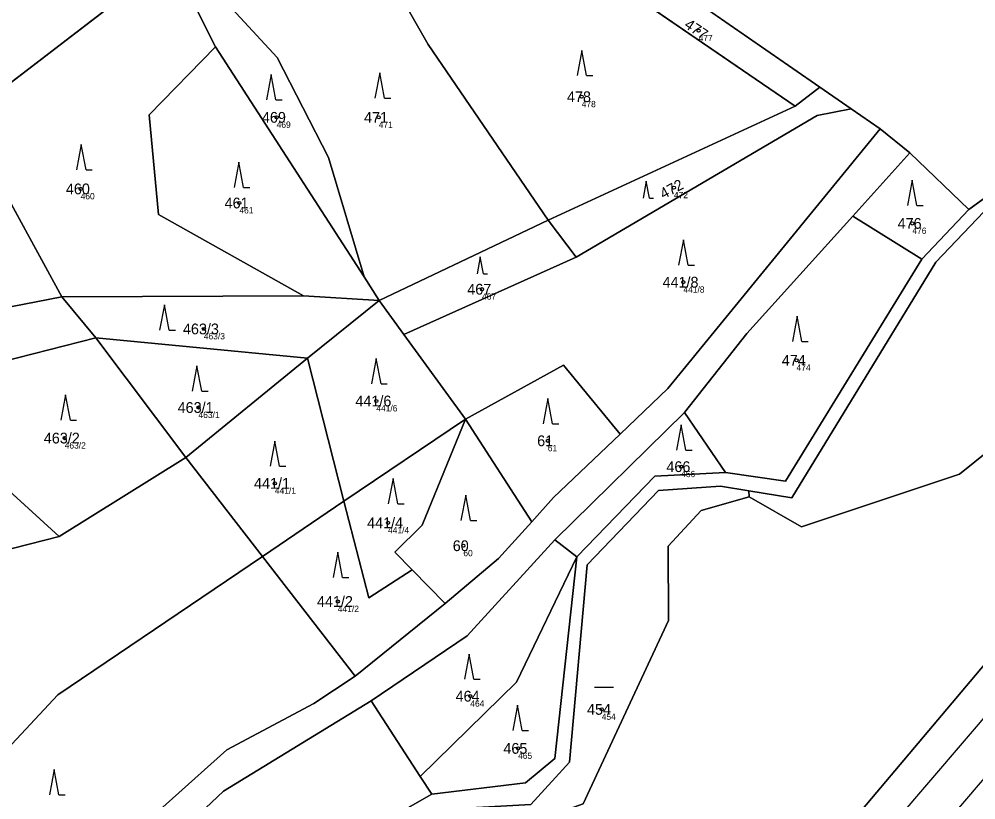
# Model space of a CAD drawing. Extents: x -554500 to -548272, y -1079733 to -1073730.
# Drawn here: x -551641.1 to -551489.7, y -1075645.3 to -1075521.8 of the extents above; entities that cross this region are included whole.
import ezdxf

# ---------------------------------------------------------------- set-up
doc = ezdxf.new("R2010")
doc.units = 0
for name, color, linetype in [('Definiční body', 7, 'Continuous'), ('Hranice parcel', 7, 'Continuous'), ('Parcelní čísla', 7, 'Continuous'), ('Polygon ku', 7, 'Continuous'), ('Polygon parcely', 7, 'Continuous'), ('Vnitřní kresba', 7, 'Continuous'), ('Značky kultur', 7, 'Continuous')]:
    doc.layers.add(name, color=color, linetype=linetype)

msp = doc.modelspace()

# ---------------------------------------------------------------- linework, layer by layer
at = {"layer": 'Definiční body'}
for centre in [(-551533.57, -1075523.64994), (-551552.07, -1075534.09994), (-551600.33, -1075537.35994), (-551584.18, -1075537.36994), (-551631.34, -1075548.67994), (-551537.48, -1075548.48994), (-551606.23, -1075550.90994), (-551499.76, -1075554.13994), (-551535.98, -1075563.43994), (-551567.84, -1075564.54994), (-551611.85, -1075570.82994), (-551518.08, -1075575.78994), (-551612.69, -1075583.25994), (-551584.56, -1075582.22994), (-551633.86, -1075588.09994), (-551557.43, -1075588.52994), (-551536.34, -1075592.61994), (-551600.61, -1075595.25994), (-551582.71, -1075601.49994), (-551570.79, -1075605.12994), (-551590.65, -1075613.94994), (-551569.69, -1075628.92994), (-551548.9, -1075631.01994), (-551562.13, -1075637.18994)]:
    msp.add_circle(centre, 0.25, dxfattribs=at)
at = {"layer": 'Hranice parcel'}
for p, q in [((-551549.56, -1075508.24), (-551514.4, -1075532.57)), ((-551554, -1075511.14), (-551518.28, -1075535.59)), ((-551616.94, -1075512.32), (-551649.75, -1075537.47)), ((-551609.99, -1075526.19), (-551616.94, -1075512.32)), ((-551586.49, -1075562.61), (-551609.99, -1075526.19)), ((-551514.4, -1075532.57), (-551518.28, -1075535.59)), ((-551514.4, -1075532.57), (-551509.43, -1075536.01)), ((-551490.82, -1075551.95), (-551465.77, -1075533.69)), ((-551518.28, -1075535.59), (-551557.39, -1075553.61)), ((-551509.43, -1075536.01), (-551504.87, -1075539.17)), ((-551634.33, -1075565.77), (-551649.75, -1075537.47)), ((-551504.87, -1075539.17), (-551500.16, -1075542.97)), ((-551500.16, -1075542.97), (-551509.17, -1075552.97)), ((-551500.16, -1075542.97), (-551490.82, -1075551.95)), ((-551498.28, -1075559.77), (-551490.82, -1075551.95)), ((-551557.39, -1075553.61), (-551584.08, -1075566.35)), ((-551552.96, -1075559.5), (-551557.39, -1075553.61)), ((-551498.28, -1075559.77), (-551509.17, -1075552.97)), ((-551580.19, -1075571.7), (-551552.96, -1075559.5)), ((-551584.08, -1075566.35), (-551586.49, -1075562.61)), ((-551634.33, -1075565.77), (-551596.07, -1075565.58)), ((-551628.95, -1075572.25), (-551634.33, -1075565.77)), ((-551596.07, -1075565.58), (-551584.08, -1075566.35)), ((-551584.08, -1075566.35), (-551595.46, -1075575.44)), ((-551584.08, -1075566.35), (-551580.19, -1075571.7)), ((-551595.46, -1075575.44), (-551628.95, -1075572.25)), ((-551628.95, -1075572.25), (-551614.69, -1075591.16)), ((-551570.46, -1075585.08), (-551580.19, -1075571.7)), ((-551595.46, -1075575.44), (-551614.69, -1075591.16)), ((-551589.67, -1075598.07), (-551595.46, -1075575.44)), ((-551535.81, -1075584.07), (-551556.33, -1075604.19)), ((-551529.31, -1075593.53), (-551535.81, -1075584.07)), ((-551570.46, -1075585.08), (-551589.67, -1075598.07)), ((-551559.98, -1075601.33), (-551570.46, -1075585.08)), ((-551634.75, -1075603.68), (-551650.56, -1075589.25)), ((-551614.69, -1075591.16), (-551634.75, -1075603.68)), ((-551614.69, -1075591.16), (-551602.58, -1075606.81)), ((-551525.61, -1075596.45), (-551525.59, -1075597.39)), ((-551602.58, -1075606.81), (-551589.67, -1075598.07)), ((-551644.48, -1075606.14), (-551634.75, -1075603.68)), ((-551552.81, -1075606.86), (-551556.33, -1075604.19)), ((-551602.58, -1075606.81), (-551587.91, -1075625.77)), ((-551573.69, -1075614.27), (-551578.9, -1075608.93)), ((-551587.91, -1075625.77), (-551573.69, -1075614.27)), ((-551577.6, -1075641.64), (-551585.38, -1075629.65)), ((-551575.78, -1075644.44), (-551577.6, -1075641.64))]:
    msp.add_line(p, q, dxfattribs=at)
for points in [[(-551557.39, -1075553.61), (-551576.36, -1075525.85), (-551588.07, -1075505.25)], [(-551586.49, -1075562.61), (-551592.14, -1075543.72), (-551600.22, -1075527.89), (-551609.92, -1075517.35)], [(-551596.07, -1075565.58), (-551619.02, -1075552.73), (-551620.47, -1075536.97), (-551609.99, -1075526.19)], [(-551465.28, -1075534.16), (-551488.46, -1075552.33), (-551496.05, -1075560.25), (-551518.81, -1075597.54), (-551525.61, -1075596.45)], [(-551552.96, -1075559.5), (-551514.83, -1075537.09), (-551509.43, -1075536.01)], [(-551504.87, -1075539.17), (-551538.42, -1075580.28), (-551545.97, -1075587.48)], [(-551509.17, -1075552.97), (-551525.92, -1075571.57), (-551535.81, -1075584.07)], [(-551529.31, -1075593.53), (-551519.81, -1075594.93), (-551498.28, -1075559.77)], [(-551634.33, -1075565.77), (-551650.34, -1075568.84), (-551660.13, -1075577.33)], [(-551650.56, -1075589.25), (-551643.78, -1075576.01), (-551628.95, -1075572.25)], [(-551545.97, -1075587.48), (-551554.92, -1075576.55), (-551570.46, -1075585.08)], [(-551459.35, -1075584.9), (-551470.49, -1075576.27), (-551492.3, -1075593.8), (-551517.28, -1075602.15), (-551525.59, -1075597.39)], [(-551570.46, -1075585.08), (-551577.29, -1075601.89), (-551581.63, -1075606.13), (-551578.9, -1075608.93)], [(-551560.75, -1075872.41), (-551564.05, -1075824.19), (-551568.79, -1075795.75), (-551568.78, -1075755.17), (-551558.84, -1075728.67), (-551539.1, -1075684.12), (-551467.34, -1075599.01), (-551459.35, -1075584.9)], [(-551545.97, -1075587.48), (-551556.55, -1075597.52), (-551559.98, -1075601.33)], [(-551552.81, -1075606.86), (-551540.49, -1075594.12), (-551529.31, -1075593.53)], [(-551525.61, -1075596.45), (-551530.1, -1075595.73), (-551539.9, -1075596.37), (-551551.19, -1075608.13), (-551553.99, -1075639.39), (-551560.09, -1075646.07), (-551576.31, -1075646.95), (-551596.7, -1075664.95)], [(-551525.59, -1075597.39), (-551533.17, -1075599.56), (-551538.37, -1075605.21), (-551538.32, -1075616.93), (-551551.82, -1075645.98), (-551566.19, -1075651.07), (-551581.91, -1075665.22), (-551587.04, -1075663.89), (-551594.66, -1075668.19)], [(-551578.9, -1075608.93), (-551585.75, -1075613.38), (-551589.67, -1075598.07)], [(-551559.98, -1075601.33), (-551565.23, -1075607.16), (-551573.69, -1075614.27)], [(-551556.33, -1075604.19), (-551570.2, -1075619.38), (-551585.38, -1075629.65)], [(-551602.58, -1075606.81), (-551634.94, -1075628.7), (-551671.23, -1075667.6), (-551664.02, -1075672.26), (-551677.4, -1075709.23)], [(-551577.6, -1075641.64), (-551562.37, -1075626.71), (-551552.81, -1075606.86)], [(-551575.78, -1075644.44), (-551560.93, -1075642.63), (-551556.33, -1075638.76), (-551552.81, -1075606.86)], [(-551587.91, -1075625.77), (-551594.43, -1075630.08), (-551608.2, -1075637.39), (-551625.4, -1075652.79), (-551648.43, -1075682.33), (-551654.36, -1075696.39), (-551656.22, -1075714.82), (-551656.78, -1075734.63), (-551655.54, -1075755.99)], [(-551585.38, -1075629.65), (-551608.75, -1075643.98), (-551622.11, -1075656.61), (-551628.14, -1075663.2), (-551643.57, -1075684.48), (-551647.9, -1075692.99), (-551651.95, -1075709.72), (-551652.68, -1075745.12)], [(-551643.77, -1075728.23), (-551642.39, -1075720.35), (-551630.63, -1075693.57), (-551623.73, -1075689.94), (-551613.7, -1075675.62), (-551597.79, -1075662.9), (-551583.64, -1075648.93), (-551575.78, -1075644.44)]]:
    msp.add_lwpolyline(points, dxfattribs=at)
at = {"layer": 'Polygon ku'}
msp.add_lwpolyline([(-551372.54, -1075528.44), (-551376.14, -1075528.04), (-551396.16, -1075525.8), (-551404.54, -1075528.55), (-551406.9, -1075529.33), (-551413.37, -1075528.01), (-551428.8, -1075524.85), (-551451.89, -1075526.88), (-551457.05, -1075527.33), (-551458.03, -1075528.04), (-551465.77, -1075533.69), (-551490.82, -1075551.95), (-551500.16, -1075542.97), (-551504.87, -1075539.17), (-551509.43, -1075536.01), (-551514.4, -1075532.57), (-551549.56, -1075508.24)], dxfattribs=at)
at = {"layer": 'Polygon parcely'}
for points in [[(-551908.78, -1075679.57), (-551762.84, -1075664.65), (-551729.75, -1075668.79), (-551720.31, -1075645.47), (-551712.09, -1075636.75), (-551699.35, -1075596.46), (-551669.74, -1075565.36), (-551659.13, -1075548.13), (-551649.75, -1075537.47), (-551616.94, -1075512.32), (-551603.86, -1075489.16), (-551600.43, -1075483.34), (-551622.04, -1075477.44), (-551671.35, -1075475.23), (-551688.86, -1075545.18), (-551707.78, -1075585.61), (-551761.67, -1075597.82), (-551774, -1075594.76), (-551845.13, -1075640.16)], [(-551557.39, -1075553.61), (-551576.36, -1075525.85), (-551588.07, -1075505.25), (-551593.22, -1075498.92), (-551609.92, -1075517.35), (-551600.22, -1075527.89), (-551592.14, -1075543.72), (-551586.49, -1075562.61), (-551584.08, -1075566.35)], [(-551577.03, -1075499.37), (-551588.07, -1075505.25), (-551576.36, -1075525.85), (-551557.39, -1075553.61), (-551518.28, -1075535.59), (-551554, -1075511.14), (-551565.72, -1075518.65), (-551572.3, -1075503.16)], [(-551549.56, -1075508.24), (-551554, -1075511.14), (-551518.28, -1075535.59), (-551514.4, -1075532.57)], [(-551619.02, -1075552.73), (-551620.47, -1075536.97), (-551609.99, -1075526.19), (-551616.94, -1075512.32), (-551649.75, -1075537.47), (-551634.33, -1075565.77), (-551596.07, -1075565.58)], [(-551586.49, -1075562.61), (-551592.14, -1075543.72), (-551600.22, -1075527.89), (-551609.92, -1075517.35), (-551616.94, -1075512.32), (-551609.99, -1075526.19)], [(-551609.99, -1075526.19), (-551620.47, -1075536.97), (-551619.02, -1075552.73), (-551596.07, -1075565.58), (-551584.08, -1075566.35), (-551586.49, -1075562.61)], [(-551514.4, -1075532.57), (-551518.28, -1075535.59), (-551557.39, -1075553.61), (-551552.96, -1075559.5), (-551514.83, -1075537.09), (-551509.43, -1075536.01)], [(-551525.61, -1075596.45), (-551525.59, -1075597.39), (-551517.28, -1075602.15), (-551492.3, -1075593.8), (-551470.49, -1075576.27), (-551459.35, -1075584.9), (-551442.88, -1075555.83), (-551465.28, -1075534.16), (-551488.46, -1075552.33), (-551496.05, -1075560.25), (-551518.81, -1075597.54)], [(-551504.87, -1075539.17), (-551509.43, -1075536.01), (-551514.83, -1075537.09), (-551552.96, -1075559.5), (-551580.19, -1075571.7), (-551570.46, -1075585.08), (-551554.92, -1075576.55), (-551545.97, -1075587.48), (-551538.42, -1075580.28)], [(-551634.33, -1075565.77), (-551649.75, -1075537.47), (-551659.13, -1075548.13), (-551660.13, -1075577.33), (-551650.34, -1075568.84)], [(-551509.17, -1075552.97), (-551498.28, -1075559.77), (-551490.82, -1075551.95), (-551500.16, -1075542.97)], [(-551580.19, -1075571.7), (-551552.96, -1075559.5), (-551557.39, -1075553.61), (-551584.08, -1075566.35)], [(-551525.92, -1075571.57), (-551535.81, -1075584.07), (-551529.31, -1075593.53), (-551519.81, -1075594.93), (-551498.28, -1075559.77), (-551509.17, -1075552.97)], [(-551644.48, -1075606.14), (-551634.75, -1075603.68), (-551650.56, -1075589.25), (-551660.13, -1075577.33), (-551669.74, -1075565.36), (-551699.35, -1075596.46), (-551697.38, -1075598.59), (-551695.64, -1075600.49), (-551684.02, -1075587.74), (-551677.92, -1075591.08), (-551662.18, -1075583.96)], [(-551643.78, -1075576.01), (-551628.95, -1075572.25), (-551634.33, -1075565.77), (-551650.34, -1075568.84), (-551660.13, -1075577.33), (-551650.56, -1075589.25)], [(-551634.33, -1075565.77), (-551628.95, -1075572.25), (-551595.46, -1075575.44), (-551584.08, -1075566.35), (-551596.07, -1075565.58)], [(-551595.46, -1075575.44), (-551589.67, -1075598.07), (-551570.46, -1075585.08), (-551580.19, -1075571.7), (-551584.08, -1075566.35)], [(-551650.56, -1075589.25), (-551634.75, -1075603.68), (-551614.69, -1075591.16), (-551628.95, -1075572.25), (-551643.78, -1075576.01)], [(-551614.69, -1075591.16), (-551595.46, -1075575.44), (-551628.95, -1075572.25)], [(-551614.69, -1075591.16), (-551602.58, -1075606.81), (-551589.67, -1075598.07), (-551595.46, -1075575.44)], [(-551545.97, -1075587.48), (-551554.92, -1075576.55), (-551570.46, -1075585.08), (-551559.98, -1075601.33), (-551556.55, -1075597.52)], [(-551540.49, -1075594.12), (-551529.31, -1075593.53), (-551535.81, -1075584.07), (-551556.33, -1075604.19), (-551552.81, -1075606.86)], [(-551570.46, -1075585.08), (-551589.67, -1075598.07), (-551585.75, -1075613.38), (-551578.9, -1075608.93), (-551581.63, -1075606.13), (-551577.29, -1075601.89)], [(-551559.98, -1075601.33), (-551570.46, -1075585.08), (-551577.29, -1075601.89), (-551581.63, -1075606.13), (-551578.9, -1075608.93), (-551573.69, -1075614.27), (-551565.23, -1075607.16)], [(-551634.75, -1075603.68), (-551644.48, -1075606.14), (-551682.06, -1075614.99), (-551682.42, -1075660.37), (-551683.07, -1075669.75), (-551683.19, -1075697.9), (-551678.15, -1075701.54), (-551680.63, -1075708.37), (-551677.4, -1075709.23), (-551664.02, -1075672.26), (-551671.23, -1075667.6), (-551634.94, -1075628.7), (-551602.58, -1075606.81), (-551614.69, -1075591.16)], [(-551596.7, -1075664.95), (-551594.66, -1075668.19), (-551587.04, -1075663.89), (-551581.91, -1075665.22), (-551566.19, -1075651.07), (-551551.82, -1075645.98), (-551538.32, -1075616.93), (-551538.37, -1075605.21), (-551533.17, -1075599.56), (-551525.59, -1075597.39), (-551525.61, -1075596.45), (-551530.1, -1075595.73), (-551539.9, -1075596.37), (-551551.19, -1075608.13), (-551553.99, -1075639.39), (-551560.09, -1075646.07), (-551576.31, -1075646.95)], [(-551578.9, -1075608.93), (-551585.75, -1075613.38), (-551589.67, -1075598.07), (-551602.58, -1075606.81), (-551587.91, -1075625.77), (-551573.69, -1075614.27)], [(-551562.37, -1075626.71), (-551552.81, -1075606.86), (-551556.33, -1075604.19), (-551570.2, -1075619.38), (-551585.38, -1075629.65), (-551577.6, -1075641.64)], [(-551671.23, -1075667.6), (-551664.02, -1075672.26), (-551677.4, -1075709.23), (-551684.35, -1075728.45), (-551674.47, -1075729.79), (-551673.31, -1075736.33), (-551691.38, -1075747.87), (-551693.88, -1075754.77), (-551655.54, -1075755.99), (-551656.78, -1075734.63), (-551656.22, -1075714.82), (-551654.36, -1075696.39), (-551648.43, -1075682.33), (-551625.4, -1075652.79), (-551608.2, -1075637.39), (-551594.43, -1075630.08), (-551587.91, -1075625.77), (-551602.58, -1075606.81), (-551634.94, -1075628.7)], [(-551552.81, -1075606.86), (-551562.37, -1075626.71), (-551577.6, -1075641.64), (-551575.78, -1075644.44), (-551560.93, -1075642.63), (-551556.33, -1075638.76)], [(-551628.14, -1075663.2), (-551643.57, -1075684.48), (-551647.9, -1075692.99), (-551651.95, -1075709.72), (-551652.68, -1075745.12), (-551643.77, -1075728.23), (-551642.39, -1075720.35), (-551630.63, -1075693.57), (-551623.73, -1075689.94), (-551613.7, -1075675.62), (-551597.79, -1075662.9), (-551583.64, -1075648.93), (-551575.78, -1075644.44), (-551577.6, -1075641.64), (-551585.38, -1075629.65), (-551608.75, -1075643.98), (-551622.11, -1075656.61)]]:
    msp.add_lwpolyline(points, close=True, dxfattribs=at)
for points in [[(-551529.75, -1075897.45), (-551530.47, -1075859.76), (-551533.26, -1075824.67), (-551537.91, -1075792.05), (-551533.46, -1075736.03), (-551509.93, -1075696.87), (-551488.01, -1075668.18), (-551441.98, -1075622.04), (-551402.75, -1075579.49), (-551376.14, -1075528.04), (-551396.16, -1075525.8), (-551404.54, -1075528.55), (-551406.9, -1075529.33), (-551413.37, -1075528.01), (-551428.8, -1075524.85), (-551442.88, -1075555.83), (-551459.35, -1075584.9), (-551467.34, -1075599.01), (-551539.1, -1075684.12), (-551558.84, -1075728.67), (-551568.78, -1075755.17), (-551568.79, -1075795.75), (-551564.05, -1075824.19), (-551560.75, -1075872.41)], [(-551465.77, -1075533.69), (-551490.82, -1075551.95), (-551498.28, -1075559.77), (-551519.81, -1075594.93), (-551529.31, -1075593.53), (-551540.49, -1075594.12), (-551552.81, -1075606.86), (-551556.33, -1075638.76), (-551560.93, -1075642.63), (-551575.78, -1075644.44), (-551583.64, -1075648.93), (-551597.79, -1075662.9), (-551613.7, -1075675.62), (-551623.73, -1075689.94), (-551630.63, -1075693.57), (-551642.39, -1075720.35), (-551643.77, -1075728.23)], [(-551643.57, -1075684.48), (-551628.14, -1075663.2), (-551622.11, -1075656.61), (-551608.75, -1075643.98), (-551585.38, -1075629.65), (-551570.2, -1075619.38), (-551556.33, -1075604.19), (-551535.81, -1075584.07), (-551525.92, -1075571.57), (-551509.17, -1075552.97), (-551500.16, -1075542.97), (-551504.87, -1075539.17), (-551538.42, -1075580.28), (-551545.97, -1075587.48), (-551556.55, -1075597.52), (-551559.98, -1075601.33), (-551565.23, -1075607.16), (-551573.69, -1075614.27), (-551587.91, -1075625.77), (-551594.43, -1075630.08), (-551608.2, -1075637.39), (-551625.4, -1075652.79), (-551648.43, -1075682.33)], [(-551640.82, -1075735.56), (-551640.12, -1075723.66), (-551639.8, -1075718.91), (-551628.96, -1075695.24), (-551622.67, -1075692.4), (-551611.04, -1075676.06), (-551596.7, -1075664.95), (-551576.31, -1075646.95), (-551560.09, -1075646.07), (-551553.99, -1075639.39), (-551551.19, -1075608.13), (-551539.9, -1075596.37), (-551530.1, -1075595.73), (-551525.61, -1075596.45), (-551518.81, -1075597.54), (-551496.05, -1075560.25), (-551488.46, -1075552.33)], [(-551558.84, -1075728.67), (-551539.1, -1075684.12), (-551467.34, -1075599.01), (-551459.35, -1075584.9), (-551470.49, -1075576.27), (-551492.3, -1075593.8), (-551517.28, -1075602.15), (-551525.59, -1075597.39), (-551533.17, -1075599.56), (-551538.37, -1075605.21), (-551538.32, -1075616.93), (-551551.82, -1075645.98), (-551566.19, -1075651.07), (-551581.91, -1075665.22), (-551587.04, -1075663.89), (-551594.66, -1075668.19), (-551622.67, -1075692.4), (-551628.96, -1075695.24), (-551639.8, -1075718.91), (-551640.12, -1075723.66), (-551626.96, -1075713.37), (-551568, -1075682.57), (-551547.47, -1075673.1), (-551580.44, -1075787.2)]]:
    msp.add_lwpolyline(points, dxfattribs=at)
at = {"layer": 'Vnitřní kresba'}
for p, q in [((-551480.51, -1075623.04), (-551515.55, -1075664.04)), ((-551477.49, -1075629.07), (-551510.92, -1075668.3))]:
    msp.add_line(p, q, dxfattribs=at)
at = {"layer": 'Značky kultur'}
for p, q in [((-551552.04, -1075526.76), (-551552.79, -1075530.76)), ((-551551.29, -1075530.76), (-551552.04, -1075526.76)), ((-551601.18, -1075530.59), (-551601.93, -1075534.59)), ((-551600.43, -1075534.59), (-551601.18, -1075530.59)), ((-551584.02, -1075530.34), (-551584.77, -1075534.34)), ((-551583.27, -1075534.34), (-551584.02, -1075530.34)), ((-551551.29, -1075530.76), (-551550.294, -1075530.76)), ((-551600.43, -1075534.59), (-551599.434, -1075534.59)), ((-551583.27, -1075534.34), (-551582.274, -1075534.34)), ((-551631.23, -1075541.67), (-551631.98, -1075545.67)), ((-551630.48, -1075545.67), (-551631.23, -1075541.67)), ((-551606.3, -1075544.44), (-551607.05, -1075548.44)), ((-551605.55, -1075548.44), (-551606.3, -1075544.44)), ((-551630.48, -1075545.67), (-551629.484, -1075545.67)), ((-551541.86, -1075547.45), (-551542.362, -1075550.13)), ((-551541.358, -1075550.13), (-551541.86, -1075547.45)), ((-551499.78, -1075547.31), (-551500.53, -1075551.31)), ((-551499.03, -1075551.31), (-551499.78, -1075547.31)), ((-551605.55, -1075548.44), (-551604.554, -1075548.44)), ((-551541.358, -1075550.13), (-551540.69, -1075550.13)), ((-551499.03, -1075551.31), (-551498.034, -1075551.31)), ((-551535.98, -1075556.74), (-551536.73, -1075560.74)), ((-551535.23, -1075560.74), (-551535.98, -1075556.74)), ((-551568.12, -1075559.43), (-551568.622, -1075562.11)), ((-551567.618, -1075562.11), (-551568.12, -1075559.43)), ((-551535.23, -1075560.74), (-551534.234, -1075560.74)), ((-551567.618, -1075562.11), (-551566.95, -1075562.11)), ((-551618.09, -1075567.03), (-551618.84, -1075571.03)), ((-551617.34, -1075571.03), (-551618.09, -1075567.03)), ((-551517.97, -1075568.81), (-551518.72, -1075572.81)), ((-551517.22, -1075572.81), (-551517.97, -1075568.81)), ((-551617.34, -1075571.03), (-551616.344, -1075571.03)), ((-551517.22, -1075572.81), (-551516.224, -1075572.81)), ((-551612.93, -1075576.69), (-551613.68, -1075580.69)), ((-551612.18, -1075580.69), (-551612.93, -1075576.69)), ((-551584.56, -1075575.53), (-551585.31, -1075579.53)), ((-551583.81, -1075579.53), (-551584.56, -1075575.53)), ((-551583.81, -1075579.53), (-551582.814, -1075579.53)), ((-551633.71, -1075581.24), (-551634.46, -1075585.24)), ((-551632.96, -1075585.24), (-551633.71, -1075581.24)), ((-551612.18, -1075580.69), (-551611.184, -1075580.69)), ((-551557.43, -1075581.83), (-551558.18, -1075585.83)), ((-551556.68, -1075585.83), (-551557.43, -1075581.83)), ((-551632.96, -1075585.24), (-551631.964, -1075585.24)), ((-551556.68, -1075585.83), (-551555.684, -1075585.83)), ((-551536.34, -1075586.01), (-551537.09, -1075590.01)), ((-551535.59, -1075590.01), (-551536.34, -1075586.01)), ((-551600.61, -1075588.56), (-551601.36, -1075592.56)), ((-551599.86, -1075592.56), (-551600.61, -1075588.56)), ((-551535.59, -1075590.01), (-551534.594, -1075590.01)), ((-551599.86, -1075592.56), (-551598.864, -1075592.56)), ((-551581.91, -1075594.49), (-551582.66, -1075598.49)), ((-551581.16, -1075598.49), (-551581.91, -1075594.49)), ((-551570.42, -1075597.14), (-551571.17, -1075601.14)), ((-551569.67, -1075601.14), (-551570.42, -1075597.14)), ((-551581.16, -1075598.49), (-551580.164, -1075598.49)), ((-551569.67, -1075601.14), (-551568.674, -1075601.14)), ((-551590.65, -1075606.14), (-551591.4, -1075610.14)), ((-551589.9, -1075610.14), (-551590.65, -1075606.14)), ((-551589.9, -1075610.14), (-551588.904, -1075610.14)), ((-551569.86, -1075622.26), (-551570.61, -1075626.26)), ((-551569.11, -1075626.26), (-551569.86, -1075622.26)), ((-551569.11, -1075626.26), (-551568.114, -1075626.26)), ((-551550.038, -1075627.51), (-551547.038, -1075627.51)), ((-551562.23, -1075630.37), (-551562.98, -1075634.37)), ((-551561.48, -1075634.37), (-551562.23, -1075630.37)), ((-551561.48, -1075634.37), (-551560.484, -1075634.37)), ((-551635.52, -1075640.51), (-551636.27, -1075644.51)), ((-551634.77, -1075644.51), (-551635.52, -1075640.51)), ((-551634.77, -1075644.51), (-551633.774, -1075644.51))]:
    msp.add_line(p, q, dxfattribs=at)

# ---------------------------------------------------------------- texts
at = {"layer": 'Definiční body'}
for s, p in [('477', (-551533.57, -1075525.306)), ('478', (-551552.07, -1075535.756)), ('469', (-551600.33, -1075539.016)), ('471', (-551584.18, -1075539.026)), ('460', (-551631.34, -1075550.336)), ('472', (-551537.48, -1075550.146)), ('461', (-551606.23, -1075552.566)), ('476', (-551499.76, -1075555.796)), ('441/8', (-551535.98, -1075565.096)), ('467', (-551567.84, -1075566.206)), ('463/3', (-551611.85, -1075572.486)), ('474', (-551518.08, -1075577.446)), ('441/6', (-551584.56, -1075583.886)), ('463/1', (-551612.69, -1075584.916)), ('463/2', (-551633.86, -1075589.756)), ('61', (-551557.43, -1075590.186)), ('466', (-551536.34, -1075594.276)), ('441/1', (-551600.61, -1075596.916)), ('441/4', (-551582.71, -1075603.156)), ('60', (-551570.79, -1075606.786)), ('441/2', (-551590.65, -1075615.606)), ('464', (-551569.69, -1075630.586)), ('454', (-551548.9, -1075632.676)), ('465', (-551562.13, -1075638.846))]:
    msp.add_text(s, height=0.999996, dxfattribs=at).set_placement(p)
at = {"layer": 'Parcelní čísla'}
for s, rotation, p in [('477', 326, (-551535.972, -1075523.054)), ('472', 28, (-551539.133, -1075550.332))]:
    msp.add_text(s, height=1.699998, rotation=rotation, dxfattribs=at).set_placement(p)
for s, p in [('478', (-551554.395, -1075534.95)), ('469', (-551602.655, -1075538.21)), ('471', (-551586.505, -1075538.22)), ('460', (-551633.665, -1075549.53)), ('461', (-551608.555, -1075551.76)), ('476', (-551502.085, -1075554.99)), ('441/8', (-551539.278, -1075564.29)), ('467', (-551570.165, -1075565.4)), ('463/3', (-551615.148, -1075571.68)), ('474', (-551520.405, -1075576.64)), ('441/6', (-551587.858, -1075583.08)), ('463/1', (-551615.988, -1075584.11)), ('463/2', (-551637.158, -1075588.95)), ('61', (-551559.106, -1075589.38)), ('466', (-551538.665, -1075593.47)), ('441/1', (-551603.908, -1075596.11)), ('441/4', (-551586.008, -1075602.35)), ('60', (-551572.466, -1075605.98)), ('441/2', (-551593.948, -1075614.8)), ('464', (-551572.015, -1075629.78)), ('454', (-551551.225, -1075631.87)), ('465', (-551564.455, -1075638.04))]:
    msp.add_text(s, height=1.699998, dxfattribs=at).set_placement(p)

doc.saveas('drawing.dxf')
